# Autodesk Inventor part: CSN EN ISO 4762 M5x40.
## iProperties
Shininess: 20.0
Length Units: 11269
Angle Units: 11279
Time Units: 11290
Mass Units: 11283
Length Display Precision: 3
Angle Display Precision: 2
Created: 2001-01
Part Number: CSN EN ISO 4762 M5x40.
Material: Steel, Mild
Document SubType Name: Modeling
Description: Bolt M5x40 CSN EN ISO 4762.
Standard: CSN EN ISO 4762
Density: 7.86
Volumn: 2.805817155661937
Area: 16.25312931541364
PropertySet Name: Model Information
Control State: 0
Master: False
Checked Out: False
BOM1: Bolt
BOM2: M5x40
BOM3: CSN EN ISO 4762
+MSCProtocol1+ProtocolID: P08052013574335968
+MSCProtocol2+Protocol: P08052013574335968<@PID>[Data]<@EL>P=0.8{mm<@EL>L=40{mm<@EL>d=5{mm<@EL>Dh=8.5{mm<@EL>k=5{mm<@EL>t=2.5{mm<@EL>s=4{mm<@EL>r1=0.2{mm<@EL>r2=0.5{mm<@EL>b=22{mm<@EL>
Revision Number: 1
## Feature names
1. ExtrusionBlind1
2. Chamfer1
3. ExtrusionBlind2
4. ExtrusionBlind3
5. Fillet1
6. Fillet2
